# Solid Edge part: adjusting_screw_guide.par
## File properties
Title: Adjusting screw guide
Author: Robert a Rhodes jr
Template: Normal.par
Last saved by: CADCIM
Revision: 4
Application: Solid Edge
Density: 0 kg/mm^3
Accuracy: 0.99
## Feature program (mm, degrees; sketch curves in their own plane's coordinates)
sketch for "unnamed Protrusion 1" plane through (0, 0, 0) normal (0, -1, 0) x-axis (1, 0, 0)
  circle centre (0, 0) radius 12.7
extrude "unnamed Protrusion 1" add finite 127 along +normal
sketch for "ExtrudedProtrusion_2" plane through (0, -127, 0) normal (0, -1, 0) x-axis (1, 0, 0)
  circle centre (0, 0) radius 9.525
extrude "ExtrudedProtrusion_2" add finite 152.4 along +normal
chamfer "Chamfer_1" setback 1.5748
sketch for "ExtrudedCutout_1" plane through (0, 0, 0) normal (0, 0, 1) x-axis (1, 0, 0)
  line (1.1811, 0) -> (1.1811, -9.398)
  line (1.1811, -9.398) -> (-1.1811, -9.398)
  line (-1.1811, -9.398) -> (-1.1811, 0)
  line (-1.1811, 0) -> (1.1811, 0)
extrude "ExtrudedCutout_1" cut finite 101.6 symmetric
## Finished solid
Body 1: solid body, 10 faces, 16 edges, 8 vertices.
  Faces by surface: plane 7, cylinder 2, cone 1
  Edges by curve: circle 8, line 8
Bounding box of the edges (mm): 25.400 x 279.400 x 25.400, from (-12.7, -279.4, -12.7) to (12.7, 0, 12.7).
Cylindrical faces by radius (mm): R9.525 x1, R12.7 x1
Conical faces (half-angle, radius in mm at the cone's reference point): 45 deg R9.525 x1
Planar faces by outward normal: +x 1, +y 3, -x 1, -y 2
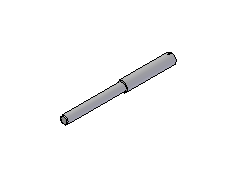
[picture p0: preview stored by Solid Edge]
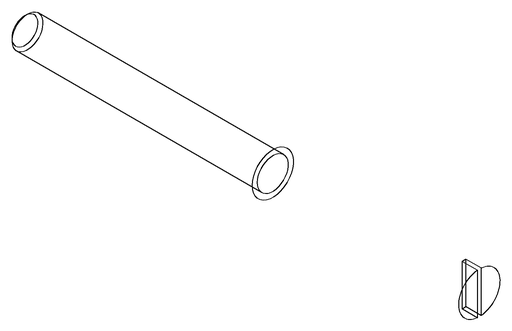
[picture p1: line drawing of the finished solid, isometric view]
